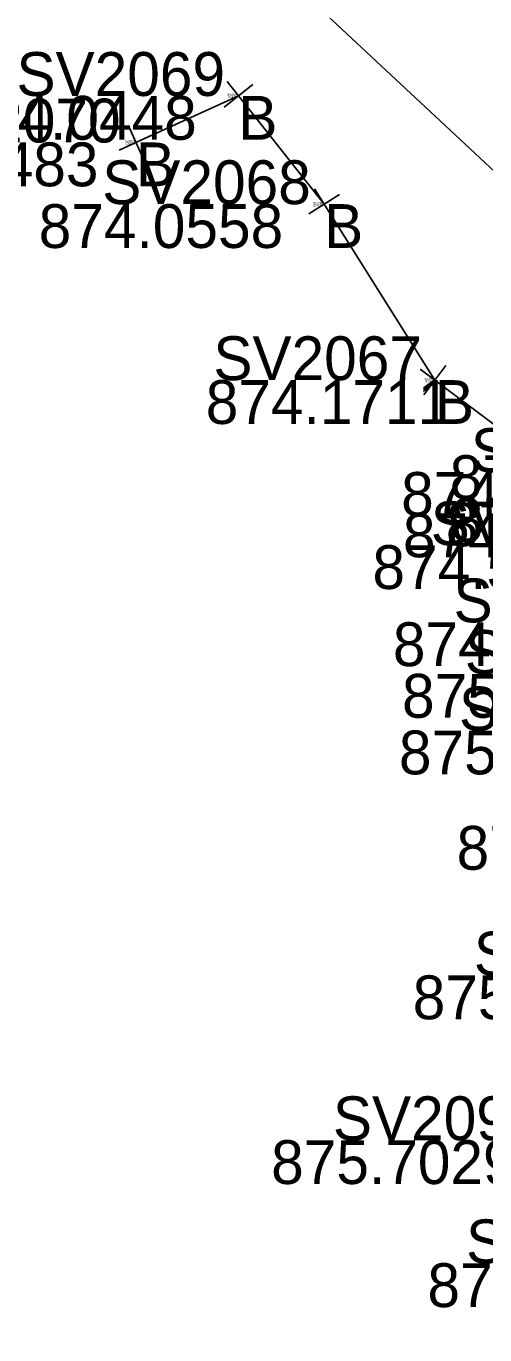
# Model space of a CAD drawing. Extents: x 1469677 to 1493262, y 375219 to 389293.
# Drawn here: x 1480042.74 to 1480055.3, y 379461.81 to 379497.65 of the extents above; entities that cross this region are included whole.
import ezdxf

# ---------------------------------------------------------------- set-up
doc = ezdxf.new("R2010")
doc.units = 0
for name, color, linetype in [('DV_X_Text', 7, 'Continuous'), ('GK_Visualization', 7, 'Continuous'), ('PNTELEV', 7, 'Continuous'), ('RW_P_Esmt_SW', 7, 'Continuous'), ('SV_X_Mon_Cells_Found', 7, 'Continuous'), ('text', 7, 'Continuous')]:
    doc.layers.add(name, color=color, linetype=linetype)

msp = doc.modelspace()

# ---------------------------------------------------------------- linework, layer by layer
at = {"layer": 'PNTELEV'}
for p, q in [((1480048.158, 379495.43), (1480048.942, 379496.051)), ((1480048.86, 379495.348), (1480048.24, 379496.132)), ((1480048.55, 379495.74), (1480048.55, 379495.74)), ((1480045.953, 379494.01), (1480045.539, 379494.92)), ((1480046.201, 379494.672), (1480045.291, 379494.258)), ((1480045.746, 379494.465), (1480045.746, 379494.465)), ((1480050.475, 379492.51), (1480051.321, 379493.042)), ((1480051.164, 379492.353), (1480050.632, 379493.199)), ((1480050.898, 379492.776), (1480050.898, 379492.776)), ((1480053.632, 379487.557), (1480054.232, 379488.357)), ((1480054.332, 379487.657), (1480053.532, 379488.257)), ((1480053.932, 379487.957), (1480053.932, 379487.957))]:
    msp.add_line(p, q, dxfattribs=at)
at = {"layer": 'SV_X_Mon_Cells_Found'}
msp.add_lwpolyline([(1477164.629, 382297.849), (1479615.888, 379904.59), (1480413.414, 379159.216)], dxfattribs=at)
at = {"layer": 'text'}
msp.add_lwpolyline([(1480061.053, 379471.656), (1480064.838, 379475.137), (1480063.063, 379477.168), (1480060.816, 379479.912), (1480059.959, 379483.437), (1480053.932, 379487.957), (1480050.898, 379492.776), (1480048.55, 379495.74), (1480045.746, 379494.465)], dxfattribs=at)

# ---------------------------------------------------------------- texts
at = {"layer": 'DV_X_Text'}
for s, height, p in [('874.0448', 1.2, (1480040.718, 379494.54)), ('874.04', 0.06, (1480048.264, 379495.68)), ('874.3483', 1.2, (1480038.027, 379493.265)), ('874.35', 0.06, (1480045.464, 379494.405)), ('874.0558', 1.2, (1480043.084, 379491.576)), ('874.06', 0.06, (1480050.608, 379492.716)), ('874.1711', 1.2, (1480047.657, 379486.757)), ('874.17', 0.06, (1480053.675, 379487.897)), ('873.8882', 1.2, (1480054.336, 379484.699)), ('874.0089', 1.2, (1480053.007, 379484.24)), ('873.9451', 1.2, (1480054.367, 379483.529)), ('874.0834', 1.2, (1480054.23, 379483.405)), ('874.0504', 1.2, (1480053.055, 379483.107)), ('874.5939', 1.2, (1480052.221, 379482.237)), ('874.8405', 1.2, (1480052.781, 379480.125)), ('875.2509', 1.2, (1480053.031, 379478.712)), ('875.5585', 1.2, (1480052.946, 379477.162)), ('875.5897', 1.2, (1480054.525, 379474.55)), ('875.4498', 1.2, (1480053.324, 379470.456)), ('875.7029', 1.2, (1480049.448, 379465.944)), ('875.7912', 1.2, (1480053.727, 379462.574))]:
    msp.add_text(s, height=height, dxfattribs=at).set_placement(p)
at = {"layer": 'GK_Visualization'}
for p in [(1480048.55, 379494.54), (1480045.746, 379493.265), (1480050.898, 379491.576), (1480053.932, 379486.757)]:
    msp.add_text('B', height=1.2, dxfattribs=at).set_placement(p)
at = {"layer": 'RW_P_Esmt_SW'}
for s, height, p in [('SV2069', 1.2, (1480042.475, 379495.74)), ('SV2070', 1.2, (1480039.614, 379494.465)), ('SV2069', 0.06, (1480048.246, 379495.74)), ('SV2070', 0.06, (1480045.439, 379494.465)), ('SV2068', 1.2, (1480044.823, 379492.776)), ('SV2068', 0.06, (1480050.594, 379492.776)), ('SV2067', 1.2, (1480047.866, 379487.957)), ('SV2067', 0.06, (1480053.629, 379487.957)), ('SV2072', 1.2, (1480054.916, 379485.44)), ('SV2066', 1.2, (1480053.818, 379483.437)), ('SV2080', 1.2, (1480054.443, 379481.325)), ('SV2065', 1.2, (1480054.75, 379479.912)), ('SV2079', 1.2, (1480054.59, 379478.362)), ('SV2062', 1.2, (1480054.997, 379471.656)), ('SV2099', 1.2, (1480051.139, 379467.144)), ('SV2096', 1.2, (1480054.785, 379463.774))]:
    msp.add_text(s, height=height, dxfattribs=at).set_placement(p)

doc.saveas('drawing.dxf')
